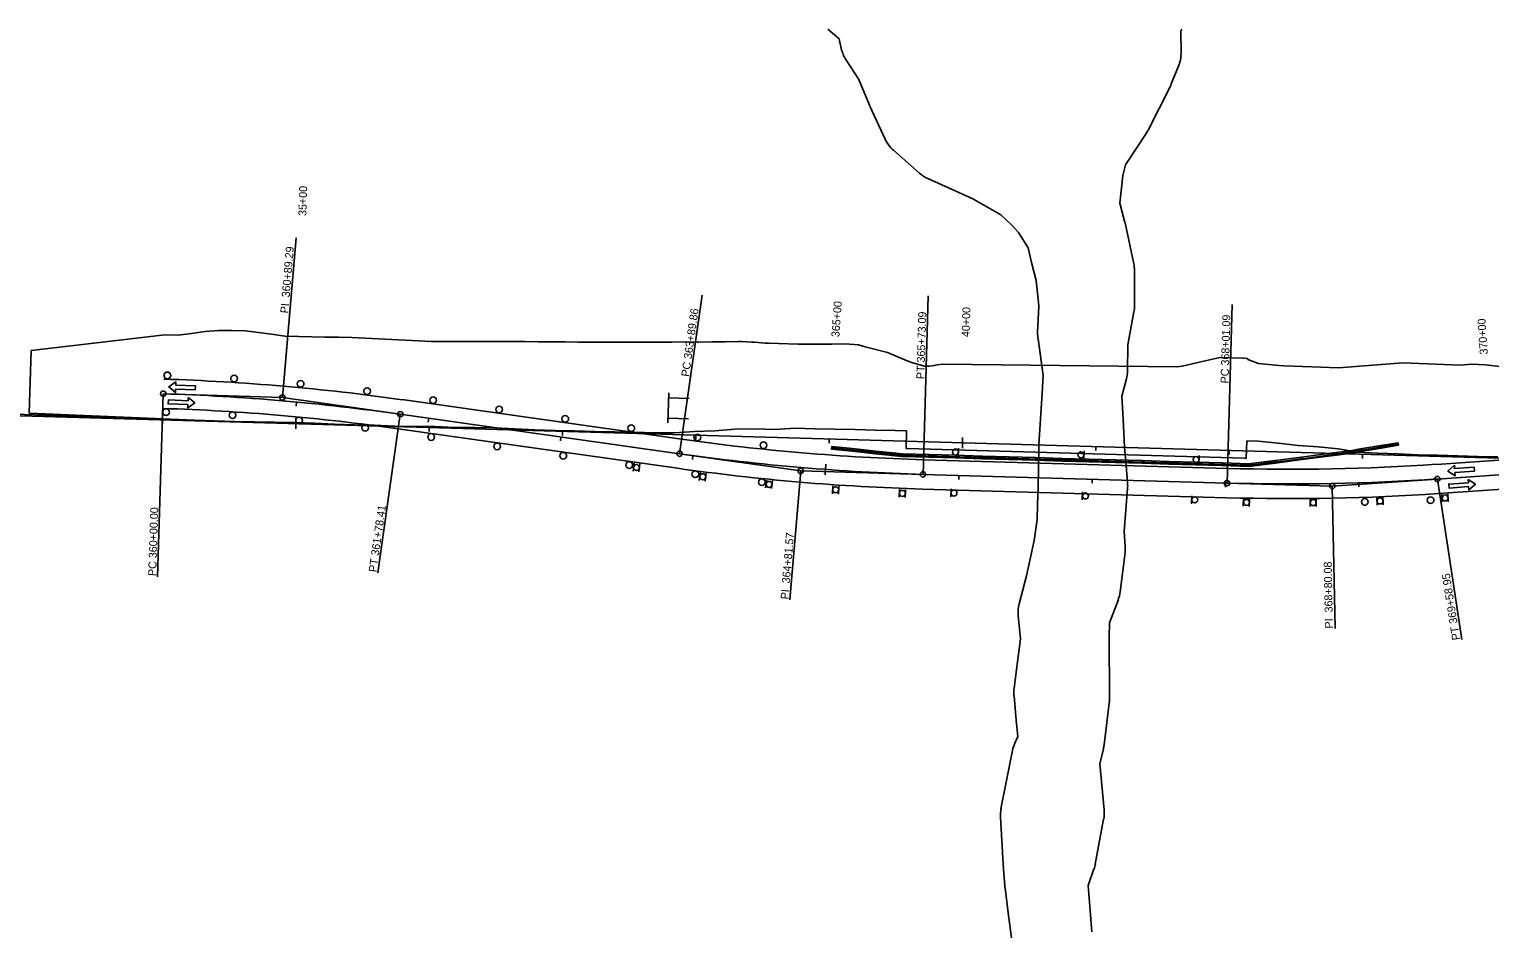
# Model space of a CAD drawing. Extents: x 976638 to 988477, y 1524676 to 1528093.
# Drawn here: x 982119 to 983214, y 1525948 to 1526629 of the extents above; entities that cross this region are included whole.
import ezdxf

# ---------------------------------------------------------------- set-up
doc = ezdxf.new("R2010")
doc.units = 0
for name, color, linetype in [('R_Draft', 7, 'Continuous'), ('R_Horz Alg', 7, 'Continuous'), ('R_Horz Alg Annot', 7, 'Continuous'), ('R_MOT', 7, 'Continuous'), ('R_No Plot', 7, 'Continuous'), ('R_Proposed Road_Lane', 7, 'Continuous'), ('R_Striping', 7, 'Continuous'), ('R_Water', 7, 'Continuous')]:
    doc.layers.add(name, color=color, linetype=linetype)

msp = doc.modelspace()

# ---------------------------------------------------------------- linework, layer by layer
at = {"layer": 'R_Draft'}
for p, q in [((982120.6, 1526388.2), (982221, 1526400)), ((982119.3, 1526341.3), (982120.6, 1526388.2)), ((982979.8, 1526376.1), (982983.6, 1526376.6)), ((983030.2, 1526307.5), (982777.3, 1526314.7))]:
    msp.add_line(p, q, dxfattribs=at)
for points in [[(982221, 1526400), (982231, 1526399.8), (982241, 1526401), (982251.1, 1526402.4), (982261.1, 1526403.3), (982271.1, 1526403.3), (982281.1, 1526403.1), (982291.1, 1526401.8), (982301, 1526400.4), (982311, 1526399.1), (982321, 1526398.7), (982331, 1526398.5), (982341, 1526398.3), (982351, 1526398.2), (982361, 1526398.1), (982371, 1526397.5), (982381, 1526397.1), (982391, 1526396.6), (982401, 1526396.1), (982411, 1526395.6), (982420.9, 1526395.1), (982430.9, 1526394.9), (982441, 1526395), (982451, 1526395), (982461, 1526394.9), (982471, 1526395), (982481, 1526394.9), (982491, 1526394.9), (982501, 1526394.8), (982511, 1526394.8), (982521, 1526394.7), (982531, 1526394.6), (982541, 1526394.6), (982544.8, 1526394.6), (982551, 1526394.6), (982561, 1526394.5), (982571, 1526394.5), (982577.8, 1526394.4), (982581, 1526394.4), (982587.8, 1526394.5), (982591, 1526394.5), (982601, 1526394.6), (982611, 1526394.7), (982619.9, 1526394.5), (982621, 1526394.5), (982631, 1526394.7), (982641, 1526394.8), (982651, 1526395), (982652.9, 1526395), (982661, 1526394.5), (982662.9, 1526394.4), (982671, 1526393.8), (982673.6, 1526393.7), (982681, 1526393.4), (982695.6, 1526393.1)], [(982695.6, 1526393.1), (982721, 1526393.1), (982731, 1526393.3), (982741, 1526392.4), (982746, 1526391.1), (982762.7, 1526386.8), (982775.7, 1526381.3), (982780.6, 1526379.3), (982790.5, 1526376.4), (982794.1, 1526376.5), (982796.1, 1526376.7), (982800.1, 1526377.4), (982803.9, 1526378), (982979.8, 1526376.1)], [(982983.6, 1526376.6), (982997.6, 1526379.8), (983011.7, 1526382.9), (983029.5, 1526382.4), (983032.5, 1526382.2), (983032.9, 1526381.5), (983040.7, 1526378.4), (983056.1, 1526377.1), (983060.1, 1526376.8), (983080.7, 1526375.9), (983100.7, 1526375.3), (983148.9, 1526378.9), (983191.9, 1526377.3), (983200.8, 1526378)], [(983200.8, 1526378), (983210.8, 1526377.5), (983230.7, 1526375.3)], [(982777, 1526327.9), (982768.3, 1526328.2), (982753.3, 1526328.6), (982738.3, 1526328.9), (982723.3, 1526329.2), (982708.2, 1526329.5), (982693.2, 1526329.9), (982678.2, 1526329.1), (982663.2, 1526329.6), (982648.2, 1526329.3), (982633.1, 1526328.1), (982618.1, 1526327.5), (982603.1, 1526326.5), (982588.1, 1526326.5), (982573.1, 1526327), (982558.1, 1526327.3), (982543.1, 1526327.6), (982528.2, 1526327.9), (982513.2, 1526328.3), (982498.2, 1526328.8), (982483.2, 1526329.5), (982468.2, 1526330.2), (982453.2, 1526330.4), (982438.2, 1526330.6), (982423.2, 1526331.2), (982408.2, 1526331.2), (982393.2, 1526331.6), (982378.2, 1526332.2), (982363.2, 1526332.4), (982348.2, 1526332.9), (982333.2, 1526333.7), (982318.2, 1526334.3), (982303.2, 1526334.6), (982288.2, 1526334.7), (982273.2, 1526335), (982258.2, 1526335.4), (982243.2, 1526336), (982119.3, 1526341.3)], [(982777.3, 1526314.7), (982776.6, 1526314.8), (982777, 1526327.9)], [(983032, 1526320.5), (983031.5, 1526307.4), (983030.2, 1526307.5)], [(983220.3, 1526308.5), (983205.3, 1526308.9), (983190.3, 1526309.2), (983175.3, 1526309.8), (983160.3, 1526310.1), (983145.3, 1526310.8), (983130.3, 1526311.4), (983115.3, 1526312), (983100.4, 1526314.5), (983085.4, 1526316.1), (983070.5, 1526317.1), (983055.5, 1526318.8), (983040.6, 1526320.3), (983032, 1526320.5)]]:
    msp.add_lwpolyline(points, dxfattribs=at)
at = {"layer": 'R_Horz Alg'}
for p, q in [((981519.5, 1526356.3), (984298.3, 1526276.6)), ((982397.4, 1526340.5), (982606.8, 1526310.9)), ((983174.9, 1526291.9), (983465.9, 1526311.7)), ((982789.2, 1526295.4), (983017.1, 1526288.8))]:
    msp.add_line(p, q, dxfattribs=at)
for centre, start, end in [((982168, 1524719.6), 81.9449, 88.1892), ((982836.2, 1527931.7), 261.9449, 268.3578), ((983064.1, 1527925.2), 268.3578, 273.883)]:
    msp.add_arc(centre, 1637, start, end, dxfattribs=at)
at = {"layer": 'R_Horz Alg Annot'}
for p, q in [((982219.7, 1526355.8), (982309, 1526353)), ((982309, 1526353), (982397.4, 1526340.5)), ((982606.8, 1526310.9), (982697.6, 1526298)), ((982697.6, 1526298), (982789.2, 1526295.4)), ((983017.1, 1526288.8), (983096.1, 1526286.6)), ((983096.1, 1526286.6), (983174.9, 1526291.9))]:
    msp.add_line(p, q, dxfattribs=at)
for points in [[(982309, 1526353), (982319.3, 1526472.6)], [(982606.8, 1526310.9), (982623.6, 1526429.7)], [(982789.3, 1526295.4), (982793.1, 1526429.3)], [(983017.2, 1526288.8), (983021.1, 1526422.8)], [(982219.7, 1526355.8), (982215.4, 1526218.7)], [(982319.3, 1526346.6), (982319.5, 1526349.6)], [(982397.4, 1526340.5), (982380.6, 1526221.7)], [(982219.1, 1526333.2), (982219.2, 1526336.2)], [(982319.2, 1526337.4), (982319, 1526329.4)], [(982418.4, 1526334.5), (982418.8, 1526337.5)], [(982419, 1526327.5), (982419.1, 1526330.5)], [(982519, 1526324.6), (982519.1, 1526327.6)], [(982517.4, 1526320.5), (982517.8, 1526323.4)], [(982618.9, 1526321.8), (982619, 1526324.8)], [(982718.9, 1526318.9), (982719, 1526321.9)], [(982819, 1526323), (982818.8, 1526315)], [(982918.8, 1526313.2), (982918.9, 1526316.2)], [(982616.4, 1526306.5), (982616.8, 1526309.5)], [(983018.8, 1526310.3), (983018.8, 1526313.3)], [(983118.7, 1526307.4), (983118.8, 1526310.4)], [(982697.6, 1526298), (982689.4, 1526201.4)], [(982716.5, 1526303.1), (982716, 1526295.1)], [(982816.1, 1526291.6), (982816.1, 1526294.6)], [(982916, 1526288.7), (982916.1, 1526291.7)], [(983016, 1526285.9), (983016.1, 1526288.9)], [(983096.1, 1526286.6), (983098.2, 1526179.9)], [(983116.1, 1526286), (983116, 1526289)], [(983193.3, 1526171.5), (983174.9, 1526291.9)]]:
    msp.add_lwpolyline(points, dxfattribs=at)
for centre in [(982219.7, 1526355.8), (982309, 1526353), (982397.4, 1526340.5), (982606.8, 1526310.9), (982697.6, 1526298), (982789.2, 1526295.4), (983017.1, 1526288.8), (983096.1, 1526286.6), (983174.9, 1526291.9)]:
    msp.add_circle(centre, 2, dxfattribs=at)
at = {"layer": 'R_MOT'}
for p, q in [((982598.7, 1526356.4), (982598, 1526333.9)), ((982614, 1526352.2), (982598.6, 1526352.7)), ((982613.4, 1526336.9), (982598.1, 1526337.4)), ((983145.4, 1526319.1), (983145.6, 1526317.2)), ((982815.9, 1526315), (982815.7, 1526309)), ((982910, 1526313), (982909.8, 1526307)), ((982996.3, 1526309.5), (982996.1, 1526303.5)), ((982571.9, 1526297.8), (982572.7, 1526303.8)), ((982577.1, 1526303.2), (982576.3, 1526297.2)), ((982621.5, 1526290.9), (982622.2, 1526296.9)), ((982626.7, 1526296.3), (982625.9, 1526290.4)), ((982671.3, 1526285.2), (982671.9, 1526291.1)), ((982676.4, 1526290.7), (982675.8, 1526284.7)), ((982721.4, 1526280.9), (982721.7, 1526286.9)), ((982726.2, 1526286.6), (982725.9, 1526280.6)), ((982771.5, 1526278.2), (982771.7, 1526284.2)), ((982776.2, 1526284), (982776, 1526278)), ((982810.2, 1526278.5), (982810.4, 1526284.5)), ((982908.7, 1526276.3), (982908.9, 1526282.3)), ((982990.6, 1526273.4), (982990.8, 1526279.4)), ((983029.4, 1526271.5), (983029.6, 1526277.5)), ((983034.1, 1526277.3), (983033.9, 1526271.3)), ((983079.6, 1526271.2), (983079.6, 1526277.2)), ((983084.1, 1526277.2), (983084.1, 1526271.2)), ((983129.8, 1526272.4), (983129.6, 1526278.4)), ((983134.1, 1526278.5), (983134.3, 1526272.5)), ((983178.5, 1526274.7), (983178.3, 1526280.7)), ((983182.8, 1526280.8), (983183, 1526274.8))]:
    msp.add_line(p, q, dxfattribs=at)
for points in [[(982733.8, 1526313), (982720.7, 1526314.4), (982721, 1526316.4), (982734, 1526315)], [(983112.7, 1526313.8), (983132.4, 1526317), (983132.8, 1526315), (983113, 1526311.8)], [(982753.7, 1526310.9), (982733.8, 1526313), (982734, 1526315), (982753.9, 1526312.9)], [(982773.5, 1526308.8), (982753.7, 1526310.9), (982753.9, 1526312.9), (982773.8, 1526310.8)], [(982773.7, 1526310.8), (982793.7, 1526310.3), (982793.6, 1526308.3), (982773.6, 1526308.8)], [(982793.7, 1526310.3), (982813.7, 1526309.7), (982813.6, 1526307.7), (982793.6, 1526308.3)], [(982813.7, 1526309.7), (982833.7, 1526309.1), (982833.6, 1526307.1), (982813.6, 1526307.7)], [(982833.7, 1526309.1), (982853.6, 1526308.5), (982853.6, 1526306.5), (982833.6, 1526307.1)], [(982853.6, 1526308.5), (982873.6, 1526308), (982873.6, 1526306), (982853.6, 1526306.5)], [(982873.6, 1526308), (982893.6, 1526307.4), (982893.6, 1526305.4), (982873.6, 1526306)], [(982893.6, 1526307.4), (982913.6, 1526306.8), (982913.6, 1526304.8), (982893.6, 1526305.4)], [(982913.6, 1526306.8), (982933.6, 1526306.2), (982933.6, 1526304.2), (982913.6, 1526304.8)], [(982933.6, 1526306.2), (982953.6, 1526305.7), (982953.5, 1526303.7), (982933.6, 1526304.2)], [(982953.6, 1526305.7), (982973.6, 1526305.1), (982973.5, 1526303.1), (982953.5, 1526303.7)], [(982973.6, 1526305.1), (982993.6, 1526304.5), (982993.5, 1526302.5), (982973.5, 1526303.1)], [(983033.4, 1526303.4), (983053.3, 1526305.9), (983053.5, 1526303.9), (983033.7, 1526301.4)], [(983053.3, 1526305.9), (983073.1, 1526308.4), (983073.3, 1526306.5), (983053.5, 1526303.9)], [(983073.1, 1526308.4), (983092.9, 1526311), (983093.2, 1526309), (983073.3, 1526306.5)], [(983092.9, 1526311), (983112.8, 1526313.5), (983113, 1526311.5), (983093.2, 1526309)], [(982993.6, 1526304.5), (983013.6, 1526304), (983013.5, 1526302), (982993.5, 1526302.5)], [(983013.6, 1526304), (983033.6, 1526303.4), (983033.5, 1526301.4), (983013.5, 1526302)]]:
    msp.add_lwpolyline(points, close=True, dxfattribs=at)
for points in [[(983145.6, 1526317.2), (983132.8, 1526315), (983132.4, 1526317), (983145.4, 1526319.1)], [(982773.6, 1526309.8), (982720.9, 1526315.4)], [(983033.5, 1526302.4), (982773.6, 1526309.8)]]:
    msp.add_lwpolyline(points, dxfattribs=at)
for centre, radius in [((982222.8, 1526369.6), 2.5), ((982272.8, 1526367.2), 2.5), ((982322.7, 1526363.3), 2.5), ((982372.5, 1526357.8), 2.5), ((982422.1, 1526351), 2.5), ((982221.8, 1526342.1), 2.5), ((982271.7, 1526339.7), 2.5), ((982321.5, 1526335.7), 2.5), ((982471.6, 1526344), 2.5), ((982521.1, 1526337), 2.5), ((982371.1, 1526330.3), 2.5), ((982570.6, 1526330), 2.5), ((982420.6, 1526323.4), 2.5), ((982470.1, 1526316.4), 2.5), ((982620.1, 1526323), 2.5), ((982669.7, 1526317.2), 2.5), ((982519.6, 1526309.4), 2.5), ((982569.1, 1526302.4), 2.5), ((982813.6, 1526312.1), 2.25), ((982907.6, 1526310), 2.25), ((982994, 1526306.5), 2.25), ((982574.5, 1526300.5), 2.25), ((982574.5, 1526300.5), 2.25), ((982618.6, 1526295.5), 2.5), ((982624.1, 1526293.6), 2.25), ((982624.1, 1526293.6), 2.25), ((982668.4, 1526289.6), 2.5), ((982673.9, 1526287.9), 2.25), ((982673.9, 1526287.9), 2.25), ((982723.8, 1526283.8), 2.25), ((982723.8, 1526283.8), 2.25), ((982773.8, 1526281.1), 2.25), ((982773.8, 1526281.1), 2.25), ((982812.5, 1526281.4), 2.25), ((982911.1, 1526279.2), 2.25), ((982993, 1526276.3), 2.25), ((983031.8, 1526274.4), 2.25), ((983031.8, 1526274.4), 2.25), ((983081.8, 1526274.2), 2.25), ((983081.8, 1526274.2), 2.25), ((983120.5, 1526274.7), 2.5), ((983131.9, 1526275.5), 2.25), ((983131.9, 1526275.5), 2.25), ((983169.8, 1526276), 2.5), ((983180.7, 1526277.7), 2.25), ((983180.7, 1526277.7), 2.25)]:
    msp.add_circle(centre, radius, dxfattribs=at)
at = {"layer": 'R_No Plot'}
msp.add_line((983030.2, 1526307.5), (982777.3, 1526314.7), dxfattribs=at)
msp.add_line((983030.2, 1526307.5), (982777.3, 1526314.7), dxfattribs=at)
for points in [[(982777, 1526327.9), (982768.3, 1526328.2), (982753.3, 1526328.6), (982738.3, 1526328.9), (982723.3, 1526329.2), (982708.2, 1526329.5), (982693.2, 1526329.9), (982678.2, 1526329.1), (982663.2, 1526329.6), (982648.2, 1526329.3), (982633.1, 1526328.1), (982618.1, 1526327.5), (982603.1, 1526326.5), (982588.1, 1526326.5), (982573.1, 1526327), (982558.1, 1526327.3), (982543.1, 1526327.6), (982528.2, 1526327.9), (982513.2, 1526328.3), (982498.2, 1526328.8), (982483.2, 1526329.5), (982468.2, 1526330.2), (982453.2, 1526330.4), (982438.2, 1526330.6), (982423.2, 1526331.2), (982408.2, 1526331.2), (982393.2, 1526331.6), (982378.2, 1526332.2), (982363.2, 1526332.4), (982348.2, 1526332.9), (982333.2, 1526333.7), (982318.2, 1526334.3), (982303.2, 1526334.6), (982288.2, 1526334.7), (982273.2, 1526335), (982258.2, 1526335.4), (982243.2, 1526336), (982228.2, 1526336.6), (982213.2, 1526337.2), (982198.2, 1526337.6), (982183.2, 1526337.8), (982168.2, 1526338.5), (982153.3, 1526339), (982138.3, 1526339.5), (982123.3, 1526339.9), (982100.8, 1526340.8)], [(982777, 1526327.9), (982768.3, 1526328.2), (982753.3, 1526328.6), (982738.3, 1526328.9), (982723.3, 1526329.2), (982708.2, 1526329.5), (982693.2, 1526329.9), (982678.2, 1526329.1), (982663.2, 1526329.6), (982648.2, 1526329.3), (982633.1, 1526328.1), (982618.1, 1526327.5), (982603.1, 1526326.5), (982588.1, 1526326.5), (982573.1, 1526327), (982558.1, 1526327.3), (982543.1, 1526327.6), (982528.2, 1526327.9), (982513.2, 1526328.3), (982498.2, 1526328.8), (982483.2, 1526329.5), (982468.2, 1526330.2), (982453.2, 1526330.4), (982438.2, 1526330.6), (982423.2, 1526331.2), (982408.2, 1526331.2), (982393.2, 1526331.6), (982378.2, 1526332.2), (982363.2, 1526332.4), (982348.2, 1526332.9), (982333.2, 1526333.7), (982318.2, 1526334.3), (982303.2, 1526334.6), (982288.2, 1526334.7), (982273.2, 1526335), (982258.2, 1526335.4), (982243.2, 1526336), (982228.2, 1526336.6), (982213.2, 1526337.2), (982198.2, 1526337.6), (982183.2, 1526337.8), (982168.2, 1526338.5), (982153.3, 1526339), (982138.3, 1526339.5), (982123.3, 1526339.9), (982100.8, 1526340.8)], [(982777.3, 1526314.7), (982776.6, 1526314.8), (982777, 1526327.9)], [(982777.3, 1526314.7), (982776.6, 1526314.8), (982777, 1526327.9)], [(983032, 1526320.5), (983031.5, 1526307.4), (983030.2, 1526307.5)], [(983032, 1526320.5), (983031.5, 1526307.4), (983030.2, 1526307.5)], [(983220.3, 1526308.5), (983205.3, 1526308.9), (983190.3, 1526309.2), (983175.3, 1526309.8), (983160.3, 1526310.1), (983145.3, 1526310.8), (983130.3, 1526311.4), (983115.3, 1526312), (983100.4, 1526314.5), (983085.4, 1526316.1), (983070.5, 1526317.1), (983055.5, 1526318.8), (983040.6, 1526320.3), (983032, 1526320.5)], [(983220.3, 1526308.5), (983205.3, 1526308.9), (983190.3, 1526309.2), (983175.3, 1526309.8), (983160.3, 1526310.1), (983145.3, 1526310.8), (983130.3, 1526311.4), (983115.3, 1526312), (983100.4, 1526314.5), (983085.4, 1526316.1), (983070.5, 1526317.1), (983055.5, 1526318.8), (983040.6, 1526320.3), (983032, 1526320.5)], [(982773.6, 1526309.8), (982720.9, 1526315.4)], [(982773.5, 1526309.8), (982773.5, 1526309.8)], [(982773.6, 1526309.8), (982773.5, 1526309.8)], [(982773.5, 1526309.8), (982773.5, 1526309.8)], [(982773.6, 1526309.8), (982773.5, 1526309.8)], [(982773.6, 1526309.8), (982773.6, 1526309.8)], [(983033.5, 1526302.4), (982773.6, 1526309.8)], [(982773.6, 1526309.8), (982773.6, 1526309.8)]]:
    msp.add_lwpolyline(points, dxfattribs=at)
msp.add_arc((982862.9, 1527919.4), 1626, 276.0249, 280.0099, dxfattribs=at)
at = {"layer": 'R_Proposed Road_Lane'}
msp.add_line((982789.6, 1526306.4), (983017.5, 1526299.8), dxfattribs=at)
at = {"layer": 'R_Striping'}
for p, q in [((982398.9, 1526351.4), (982608.3, 1526321.7)), ((982397.4, 1526340.5), (982606.8, 1526310.9)), ((982395.9, 1526329.6), (982605.2, 1526300)), ((983174.2, 1526302.9), (983465.2, 1526322.7)), ((983174.9, 1526291.9), (983465.9, 1526311.7)), ((982789.2, 1526295.4), (983017.1, 1526288.8)), ((983175.7, 1526281), (983466.7, 1526300.7)), ((982788.9, 1526284.4), (983016.8, 1526277.8))]:
    msp.add_line(p, q, dxfattribs=at)
for points in [[(982229.2, 1526364.8), (982223.9, 1526360.9), (982229, 1526356.8), (982229, 1526359.3), (982243.7, 1526358.8), (982243.8, 1526361.8), (982229.1, 1526362.3)], [(982238.4, 1526353.1), (982243.4, 1526349), (982238.1, 1526345.2), (982238.1, 1526347.7), (982223.4, 1526348.2), (982223.6, 1526351.2), (982238.3, 1526350.6)], [(983187.6, 1526302.2), (983182.7, 1526297.8), (983188.2, 1526294.2), (983188, 1526296.7), (983202.6, 1526297.8), (983202.4, 1526300.8), (983187.7, 1526299.7)], [(983197.9, 1526291.6), (983203.4, 1526288), (983198.5, 1526283.7), (983198.3, 1526286.2), (983183.6, 1526285.1), (983183.4, 1526288.1), (983198.1, 1526289.1)]]:
    msp.add_lwpolyline(points, close=True, dxfattribs=at)
for centre, radius, start, end in [((982168, 1524719.6), 1648, 81.9449, 88.1892), ((982168, 1524719.6), 1637, 81.9449, 88.1892), ((982168, 1524719.6), 1626, 81.9449, 88.1892), ((982836.2, 1527931.7), 1626, 261.9449, 268.3578), ((982836.2, 1527931.7), 1637, 261.9449, 268.3578), ((982836.2, 1527931.7), 1648, 261.9449, 268.3578), ((983064.1, 1527925.2), 1626, 268.3578, 273.883), ((983064.1, 1527925.2), 1637, 268.3578, 273.883), ((983064.1, 1527925.2), 1648, 268.3578, 273.883)]:
    msp.add_arc(centre, radius, start, end, dxfattribs=at)
at = {"layer": 'R_Water'}
for p, q in [((982975.4, 1526588), (982980.9, 1526601.4)), ((982958, 1526553.5), (982974.5, 1526586)), ((982760.9, 1526546.7), (982749.5, 1526571.3)), ((982786.6, 1526521.2), (982767.1, 1526538.4)), ((982947.3, 1526453.3), (982940.7, 1526484)), ((982937.1, 1526207.4), (982940.7, 1526236.8)), ((982927, 1526109.3), (982929, 1526126)), ((982925, 1526092.7), (982927, 1526109.3)), ((982847.7, 1526044.8), (982856.3, 1526088.4)), ((982848.8, 1526012.3), (982847.3, 1526038.5)), ((982918.4, 1526003.3), (982924.7, 1526037))]:
    msp.add_line(p, q, dxfattribs=at)
for points in [[(982728, 1526614.6), (982726.4, 1526621.8), (982718, 1526629.1)], [(982982.7, 1526610.8), (982982.6, 1526627.6), (982983.4, 1526629.1)], [(982749.1, 1526572.2), (982741.1, 1526591.3), (982731.4, 1526606.4)], [(982940.4, 1526485.2), (982936.7, 1526498.7), (982939, 1526519.4), (982941.1, 1526527.5), (982956.6, 1526551)], [(982875.2, 1526401.6), (982876.1, 1526421.8), (982874, 1526440.8), (982870.7, 1526454.3), (982868, 1526465.3), (982860.9, 1526476.6), (982856.1, 1526482), (982847.7, 1526490), (982826.7, 1526501.9), (982792.9, 1526517.1)], [(982947.8, 1526421.7), (982947.8, 1526434.9), (982947.8, 1526448)], [(982942.6, 1526373.1), (982942.9, 1526392.6), (982947.4, 1526417.2)], [(982876, 1526317.6), (982878.6, 1526356.3), (982879.4, 1526369.6), (982875.5, 1526397)], [(982942.6, 1526288.7), (982941.5, 1526302.4), (982940.4, 1526315.8), (982939.3, 1526336.7), (982938.4, 1526354.1), (982941.8, 1526367)], [(982861.3, 1526198.3), (982866.8, 1526219.3), (982872.6, 1526245.9), (982874.9, 1526261.6), (982875.2, 1526272.7), (982875.5, 1526285.3), (982876, 1526316.3)], [(982940.8, 1526241.4), (982940.1, 1526252.8), (982942.6, 1526284.7)], [(982929.1, 1526129), (982928.9, 1526173), (982929.1, 1526184.1), (982935.7, 1526201.6)], [(982857.6, 1526135.1), (982860.1, 1526154.9), (982862.4, 1526172), (982860.6, 1526189.5)], [(982858.1, 1526093.8), (982860.3, 1526098.9), (982859.2, 1526110.9), (982857.5, 1526129.5)], [(982925.1, 1526043.9), (982921.8, 1526078.5), (982924.5, 1526089.7)], [(982850.6, 1525987), (982849.7, 1525999.5), (982848.9, 1526012)], [(982915.8, 1525952.6), (982913.1, 1525987.2), (982917.4, 1525999.7)], [(982855.7, 1525948), (982853.2, 1525966.8), (982850.8, 1525985.5)]]:
    msp.add_lwpolyline(points, dxfattribs=at)
for centre, start, end in [((982752.4, 1526619.9), 192.3993, 212.8418), ((982957.7, 1526610.8), 338.019, 0.1074), ((982952.2, 1526597.3), 333.1076, 338.019), ((982772.2, 1526581.8), 202.7105, 204.7707), ((982783.6, 1526557.1), 204.7707, 228.6621), ((982935.7, 1526564.8), 326.525, 333.1076), ((982803.1, 1526539.9), 228.6621, 245.7507), ((982916.2, 1526478.7), 12.1798, 15.0527), ((982922.8, 1526448.1), 359.9434, 12.1798), ((982922.8, 1526421.7), 349.5549, 359.9477), ((982900.2, 1526400.5), 177.5261, 188.1314), ((982917.6, 1526373.4), 345.2069, 359.2686), ((982901, 1526315.9), 176.1834, 179.0605), ((982917.7, 1526286.7), 355.5437, 4.6093), ((982915.9, 1526239.8), 353.092, 3.5498), ((982912.3, 1526210.4), 339.2653, 353.092), ((982885.5, 1526192), 165.3972, 185.7089), ((982882.3, 1526131.8), 172.5638, 185.3756), ((982904.1, 1526128.9), 353.291, 0.2617), ((982902.2, 1526112.3), 353.2876, 353.291), ((982880.9, 1526083.6), 155.8902, 168.8153), ((982900.2, 1526095.6), 346.3908, 353.2876), ((982872.3, 1526040), 168.8153, 183.347), ((982900.2, 1526041.6), 349.3756, 5.382), ((982873.8, 1526013.8), 183.347, 184.0204), ((982893.9, 1526007.9), 340.6519, 349.3756), ((982875.5, 1525988.8), 184.0155, 187.4527)]:
    msp.add_arc(centre, 25, start, end, dxfattribs=at)

# ---------------------------------------------------------------- texts
at = {"layer": 'R_Horz Alg Annot'}
for s, rotation, p in [('35+00', 88.3578, (982327, 1526489)), ('PI  360+89.29', 85.0671, (982313.4, 1526415.9)), ('PC 363+89.86', 81.9449, (982613.9, 1526368.3)), ('365+00', 85.7997, (982726.5, 1526398.1)), ('PT 365+73.09', 88.3578, (982790.3, 1526366.7)), ('40+00', 88.3578, (982824.2, 1526398.2)), ('PC 368+01.09', 88.3578, (983018.3, 1526363.5)), ('370+00', 93.883, (983212.7, 1526385.4)), ('PC 360+00.00', 88.1892, (982214.4, 1526219.1)), ('PT 361+78.41', 81.9449, (982379.6, 1526221.8)), ('PI  364+81.57', 85.1513, (982688.4, 1526201.5)), ('PI  368+80.08', 91.1204, (983096.6, 1526179.9)), ('PT 369+58.95', 99.0035, (983192, 1526171.6))]:
    msp.add_text(s, height=6, rotation=rotation, dxfattribs=at).set_placement(p)

doc.saveas('drawing.dxf')
